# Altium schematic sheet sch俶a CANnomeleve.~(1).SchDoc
size A4
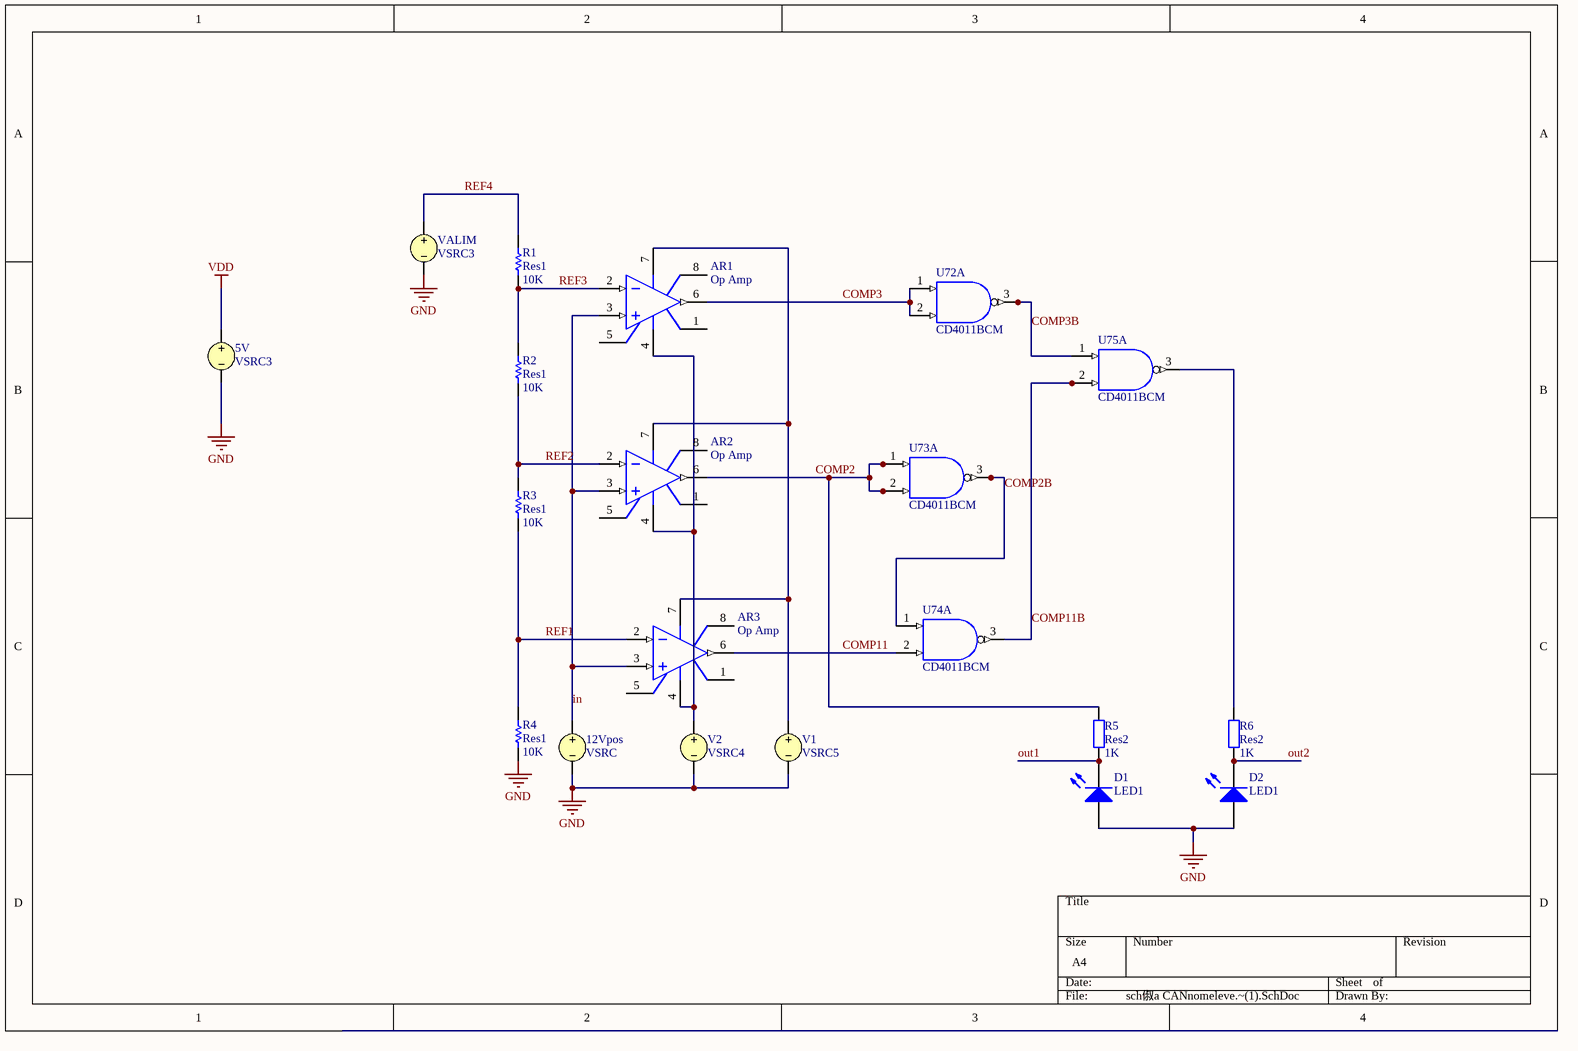
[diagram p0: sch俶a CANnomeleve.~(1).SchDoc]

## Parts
5V  VSRC3
12Vpos  VSRC
AR1  Op Amp  [H-08A]
AR2  Op Amp  [H-08A]
AR3  Op Amp  [H-08A]
D1  LED1  [LED-1]
D2  LED1  [LED-1]
R1  Res1  value 10K  [AXIAL-0.3]
R2  Res1  value 10K  [AXIAL-0.3]
R3  Res1  value 10K  [AXIAL-0.3]
R4  Res1  value 10K  [AXIAL-0.3]
R5  Res2  value 1K  [AXIAL-0.4]
R6  Res2  value 1K  [AXIAL-0.4]
U72  CD4011BCM  [M14A_N]  (part A of 4)
U73  CD4011BCM  [M14A_N]  (part A of 4)
U74  CD4011BCM  [M14A_N]  (part A of 4)
U75  CD4011BCM  [M14A_N]  (part A of 4)
V1  VSRC5
V2  VSRC4
VALIM  VSRC3

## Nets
GND: 5V.2 12Vpos.2 D1.1(A) D2.1(A) R4.1 U72.7(GND) U73.7(GND) U74.7(GND) U75.7(GND) V1.2 V2.2 VALIM.2
VDD: 5V.1 U72.14(VDD) U73.14(VDD) U74.14(VDD) U75.14(VDD)
COMP2: AR2.6(OUT) R5.2 U73.1(A) U73.2(B)
COMP2B: U73.3(J) U74.1(A)
COMP3: AR1.6(OUT) U72.1(A) U72.2(B)
COMP3B: U72.3(J) U75.1(A)
COMP11: AR3.6(OUT) U74.2(B)
COMP11B: U74.3(J) U75.2(B)
in: 12Vpos.1 AR1.3(IN+) AR2.3(IN+) AR3.3(IN+)
out1: D1.2(K) R5.1
out2: D2.2(K) R6.1
REF1: AR3.2(IN-) R3.1 R4.2
REF2: AR2.2(IN-) R2.1 R3.2
REF3: AR1.2(IN-) R1.1 R2.2
REF4: R1.2 VALIM.1
NetAR1_4: AR1.4(V-) AR2.4(V-) AR3.4(V-) V2.1
NetAR1_7: AR1.7(V+) AR2.7(V+) AR3.7(V+) V1.1
NetR6_2: R6.2 U75.3(J)

Not connected (* = marked no-connect by the designer): AR1 1(OS_NUL) 5(OS_NUL) 8(TAB); AR2 1(OS_NUL) 5(OS_NUL) 8(TAB); AR3 1(OS_NUL) 5(OS_NUL) 8(TAB)

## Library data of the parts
5V = VSRC: Voltage Source; Note: PCB Footprint - Not required; Value: +5
12Vpos = VSRC: Voltage Source; Note: PCB Footprint - Not required; Value: 10
AR1-AR3 = Op Amp: FET Operational Amplifier
D1 D2 = LED1: Typical RED GaAs LED
R1-R4 = Res1: Resistor
R5 R6 = Res2: Resistor
U72-U75 = CD4011BCM: Quad 2-Input NAND Buffered B series Gate, 14-Pin SOIC; IC_Technology: C
V1 = VSRC: Voltage Source; Note: PCB Footprint - Not required; Value: +15
V2 = VSRC: Voltage Source; Note: PCB Footprint - Not required; Value: -15
VALIM = VSRC: Voltage Source; Note: PCB Footprint - Not required; Value: +12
